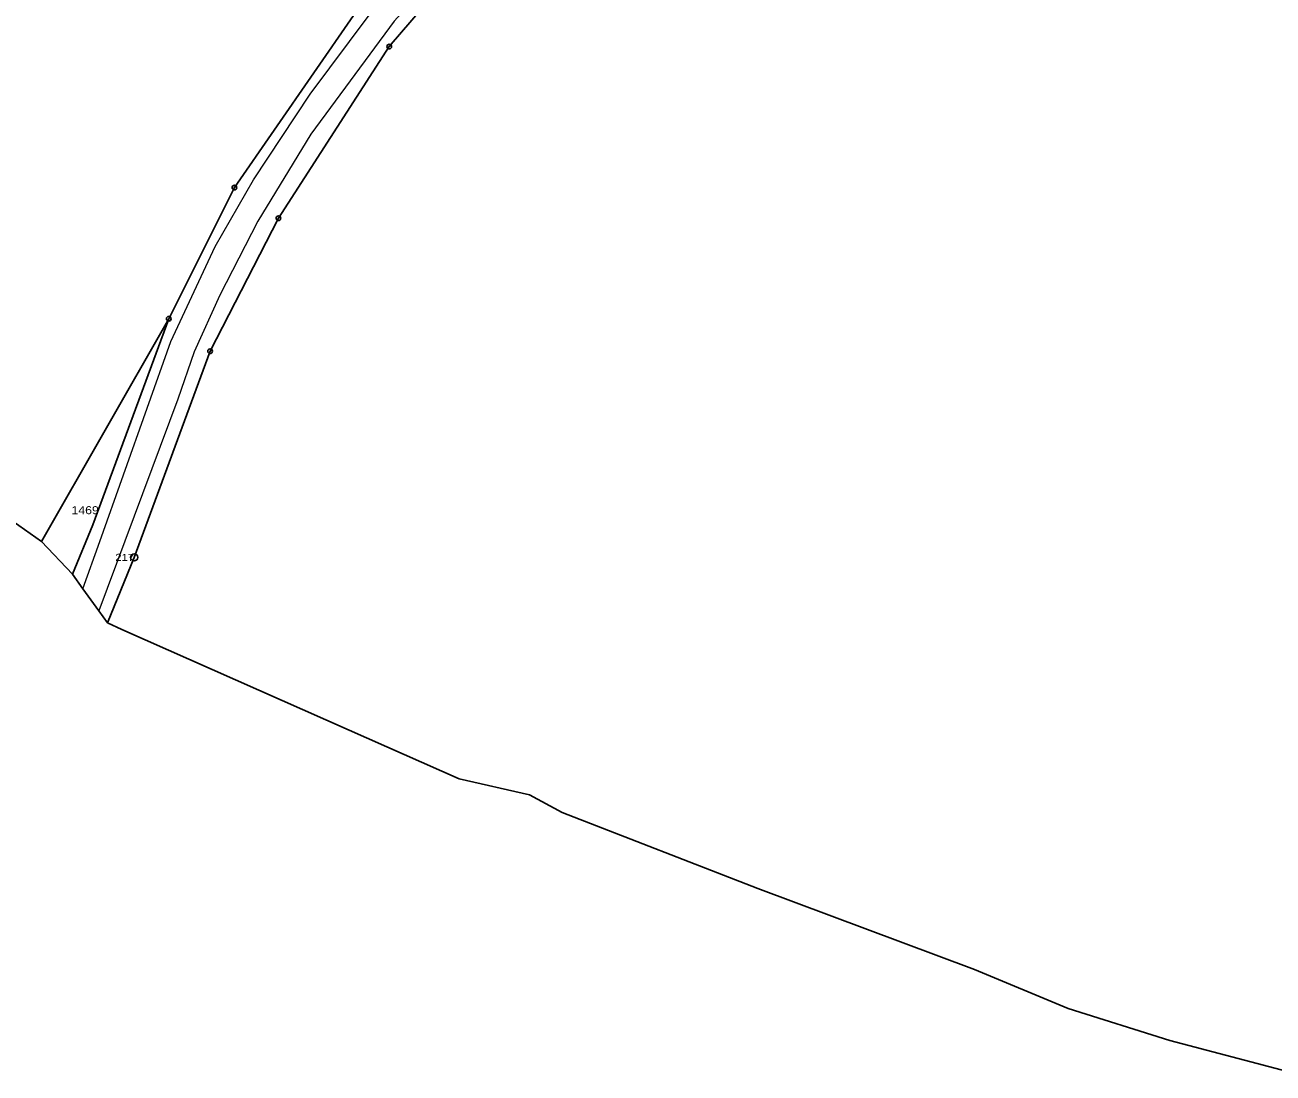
# Model space of a CAD drawing. Extents: x -872229 to -869198, y -1075981 to -1074329.
# Drawn here: x -871472.2 to -871207, y -1075817.5 to -1075594.7 of the extents above; entities that cross this region are included whole.
import ezdxf
from ezdxf.enums import TextEntityAlignment as Align

# ---------------------------------------------------------------- set-up
doc = ezdxf.new("R2010")
doc.units = 0
doc.header["$LTSCALE"] = 0.68
for name, color, linetype, lineweight in [('1', 7, 'Continuous', 25), ('4', 7, 'Continuous', 13), ('8', 7, 'Continuous', 25)]:
    doc.layers.add(name, color=color, linetype=linetype, lineweight=lineweight)
doc.layers.add('2', color=7, linetype='Continuous')

msp = doc.modelspace()

# ---------------------------------------------------------------- linework, layer by layer
at = {"layer": '1'}
for p, q in [((-871462.11, -1075711.44), (-871468.69, -1075704.44)), ((-871451.56, -1075723.14), (-871454.61, -1075721.79)), ((-871228.89, -1075810.51), (-871202.55, -1075817.46))]:
    msp.add_line(p, q, dxfattribs=at)
for points in [[(-871212.24, -1075392.84), (-871252.68, -1075434.13), (-871377.15, -1075563.45), (-871402.35, -1075592.63), (-871427.67, -1075629.24), (-871441.61, -1075657.13), (-871468.69, -1075704.44)], [(-871309.29, -1075507.4), (-871370.19, -1075570.62), (-871394.77, -1075599.26), (-871418.31, -1075635.76), (-871432.83, -1075664.02), (-871448.97, -1075707.84), (-871454.61, -1075721.79)], [(-871468.69, -1075704.44), (-871508.48, -1075676.4), (-871526.27, -1075654.51), (-871546.4, -1075620.32), (-871556.03, -1075596.19)], [(-871441.61, -1075657.13), (-871457.75, -1075700.95), (-871462.11, -1075711.44)], [(-871454.61, -1075721.79), (-871456.47, -1075719.22), (-871459.85, -1075714.56), (-871462.11, -1075711.44)], [(-871451.56, -1075723.14), (-871403.27, -1075744.54), (-871379.92, -1075754.89)], [(-871379.92, -1075754.89), (-871364.99, -1075758.34), (-871358.07, -1075762.05)], [(-871358.07, -1075762.05), (-871316.43, -1075778.25), (-871270.44, -1075795.48)], [(-871270.44, -1075795.48), (-871250.55, -1075803.77), (-871228.89, -1075810.51)]]:
    msp.add_lwpolyline(points, dxfattribs=at)
at = {"layer": '4'}
for p, q in [((-871431.74, -1075641.73), (-871423.61, -1075627.58)), ((-871422.7, -1075636.35), (-871430.78, -1075652.09)), ((-871441.17, -1075661.93), (-871431.74, -1075641.73)), ((-871456.27, -1075704.47), (-871441.17, -1075661.93)), ((-871439.7, -1075674.21), (-871456.47, -1075719.22)), ((-871459.85, -1075714.56), (-871456.27, -1075704.47))]:
    msp.add_line(p, q, dxfattribs=at)
for points in [[(-871370.95, -1075568.72), (-871393.73, -1075593.84), (-871411.43, -1075617.88), (-871422.7, -1075636.35)], [(-871423.61, -1075627.58), (-871411.59, -1075609.37), (-871394.86, -1075586.88)], [(-871430.78, -1075652.09), (-871436.26, -1075664.18), (-871439.7, -1075674.21)]]:
    msp.add_lwpolyline(points, dxfattribs=at)
at = {"layer": '8'}
for centre, radius in [((-871394.77, -1075599.2599), 0.5), ((-871394.77, -1075599.2599), 0.0303), ((-871427.67, -1075629.2399), 0.5), ((-871427.67, -1075629.2399), 0.0303), ((-871418.31, -1075635.7599), 0.5), ((-871418.31, -1075635.7599), 0.0303), ((-871441.61, -1075657.1299), 0.5), ((-871441.61, -1075657.1299), 0.0303), ((-871432.83, -1075664.0199), 0.5), ((-871432.83, -1075664.0199), 0.0303), ((-871448.97, -1075707.8398), 0.75), ((-871448.97, -1075707.8398), 0.03)]:
    msp.add_circle(centre, radius, dxfattribs=at)

# ---------------------------------------------------------------- texts
at = {"layer": '2', "width": 1.15}
msp.add_text('1469', height=1.7, dxfattribs=at).set_placement((-871462.3, -1075698.66))
at = {"layer": '8', "width": 1.2}
msp.add_text('217', height=1.5, dxfattribs=at).set_placement((-871448.97, -1075708.59), align=Align.RIGHT)

doc.saveas('drawing.dxf')
